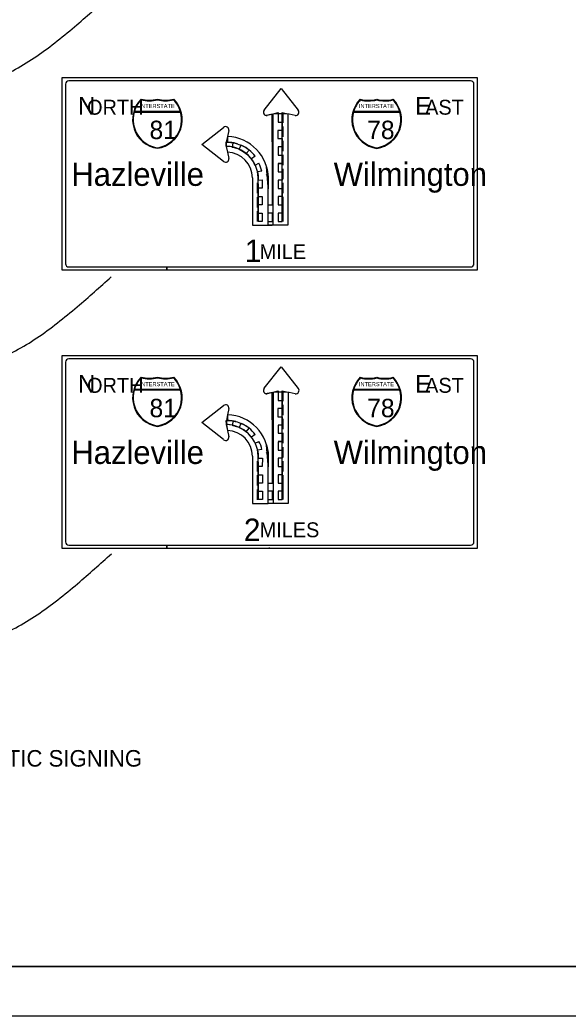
# Model space of a CAD drawing. Extents: x 640994 to 644422, y 298458 to 299646.
# Drawn here: x 642036.9 to 642202.5, y 298457.6 to 298758.5 of the extents above; entities that cross this region are included whole.
import ezdxf

# ---------------------------------------------------------------- set-up
doc = ezdxf.new("R2010")
doc.units = 0
for name, color, linetype in [('1', 7, 'Continuous'), ('2', 7, 'Continuous'), ('XCS-GRID-MIN', 7, 'Continuous')]:
    doc.layers.add(name, color=color, linetype=linetype)

msp = doc.modelspace()

# ---------------------------------------------------------------- linework, layer by layer
at = {"layer": '1'}
for p, q in [((642661.31, 298472.63), (641875.31, 298472.63)), ((641875.31, 298472.63), (642461.31, 298472.63))]:
    msp.add_line(p, q, dxfattribs=at)
at = {"layer": '2'}
for p, q in [((642049.69, 298682.88), (642049.69, 298741.13)), ((642049.69, 298741.13), (642175.06, 298741.13)), ((642049.69, 298740.13), (642049.69, 298740.13)), ((642050.69, 298739.13), (642050.69, 298684.88)), ((642173.06, 298740.13), (642051.69, 298740.13)), ((642174.06, 298684.88), (642174.06, 298739.13)), ((642175.06, 298741.13), (642175.06, 298682.88)), ((642175.06, 298740.13), (642175.06, 298740.13)), ((642110.71, 298731.28), (642115.83, 298737.78)), ((642115.83, 298737.78), (642120.98, 298731.22)), ((642073.56, 298734.38), (642073.56, 298734.38)), ((642078.44, 298734.38), (642078.44, 298734.38)), ((642083.31, 298734.38), (642083.31, 298734.38)), ((642139.81, 298734.38), (642139.81, 298734.38)), ((642144.69, 298734.38), (642144.69, 298734.38)), ((642149.56, 298734.38), (642149.56, 298734.38)), ((642061.94, 298732.13), (642061.94, 298732.13)), ((642061.94, 298732.13), (642061.94, 298732.13)), ((642061.94, 298732.13), (642061.94, 298732.13)), ((642061.94, 298732.13), (642061.94, 298732.13)), ((642061.94, 298732.13), (642061.94, 298732.13)), ((642071.44, 298730.63), (642085.44, 298730.63)), ((642085.44, 298730.88), (642071.56, 298730.88)), ((642110.69, 298731.22), (642110.71, 298731.28)), ((642113.13, 298730), (642111.25, 298729.63)), ((642113.46, 298730.03), (642111.58, 298729.65)), ((642113.46, 298730.03), (642111.61, 298729.63)), ((642113.13, 298730.03), (642114.88, 298730.52)), ((642114.94, 298730.15), (642113.46, 298730.03)), ((642113.46, 298696.53), (642113.46, 298730.03)), ((642114.88, 298730.52), (642114.88, 298727.62)), ((642116.1, 298730.15), (642114.94, 298730.15)), ((642118.21, 298730.03), (642116.1, 298730.15)), ((642116.13, 298697.65), (642116.13, 298730.53)), ((642116.13, 298730.53), (642117.88, 298730.1)), ((642116.13, 298727.38), (642116.13, 298730.5)), ((642116.46, 298727.4), (642116.46, 298730.53)), ((642117.88, 298730.1), (642117.88, 298696.5)), ((642120.06, 298729.63), (642118.21, 298730.03)), ((642151.69, 298730.88), (642137.69, 298730.88)), ((642137.69, 298730.63), (642151.69, 298730.63)), ((642162.81, 298732.13), (642162.81, 298732.13)), ((642162.81, 298732.13), (642162.81, 298732.13)), ((642078.44, 298727.13), (642078.44, 298727.13)), ((642114.88, 298727.62), (642116.11, 298727.62)), ((642116.11, 298727.62), (642116.11, 298725.13)), ((642144.69, 298727.13), (642144.69, 298727.13)), ((642091.88, 298720.9), (642098.38, 298726.03)), ((642100, 298725.15), (642099.63, 298723.28)), ((642116.11, 298725.13), (642114.81, 298725.13)), ((642114.81, 298725.13), (642114.81, 298722.67)), ((642116.13, 298723.13), (642116.13, 298726.25)), ((642116.46, 298723.15), (642116.46, 298726.28)), ((642098.38, 298715.78), (642091.88, 298720.9)), ((642099.63, 298723.27), (642099.25, 298721.55)), ((642099.25, 298721.53), (642099.25, 298720.28)), ((642114.81, 298722.67), (642116.12, 298722.67)), ((642116.12, 298722.67), (642116.12, 298720.14)), ((642116.13, 298718.88), (642116.13, 298722)), ((642116.46, 298718.9), (642116.46, 298722.03)), ((642099.22, 298720.32), (642099.63, 298718.52)), ((642099.25, 298720.28), (642099.63, 298718.53)), ((642099.63, 298718.53), (642100, 298716.65)), ((642116.12, 298720.14), (642114.88, 298720.14)), ((642114.88, 298720.14), (642114.88, 298717.69)), ((642114.88, 298717.69), (642116.14, 298717.69)), ((642116.13, 298714.63), (642116.13, 298717.75)), ((642116.14, 298717.69), (642116.14, 298715.15)), ((642116.46, 298714.65), (642116.46, 298717.78)), ((642107.96, 298717.31), (642106.85, 298716.51)), ((642107.98, 298714.65), (642109.08, 298715.22)), ((642116.14, 298715.15), (642114.88, 298715.15)), ((642114.88, 298715.15), (642114.88, 298715.15)), ((642114.88, 298715.15), (642116.11, 298715.15)), ((642116.11, 298715.14), (642114.88, 298715.14)), ((642114.88, 298715.14), (642114.88, 298712.63)), ((642116.11, 298715.15), (642116.11, 298715.14)), ((642109.98, 298712.79), (642108.66, 298712.63)), ((642111.42, 298714.08), (642111.39, 298714.15)), ((642111.39, 298714.15), (642111.6, 298713.35)), ((642111.87, 298711.17), (642111.4, 298711.94)), ((642111.4, 298711.94), (642111.88, 298711.08)), ((642111.6, 298713.35), (642111.72, 298712.74)), ((642111.72, 298712.74), (642111.83, 298711.84)), ((642111.83, 298711.84), (642111.87, 298711.17)), ((642114.88, 298712.63), (642116.13, 298712.63)), ((642116.13, 298710.38), (642116.13, 298713.5)), ((642116.13, 298712.63), (642116.13, 298710.15)), ((642116.46, 298710.4), (642116.46, 298713.53)), ((642107.13, 298710.78), (642107.13, 298696.5)), ((642108.55, 298709.25), (642108.55, 298706.13)), ((642108.9, 298697.66), (642108.86, 298710.83)), ((642108.87, 298709.04), (642108.88, 298706.15)), ((642110.12, 298710.16), (642110.11, 298707.65)), ((642111.87, 298696.5), (642111.88, 298710.5)), ((642111.87, 298707.53), (642111.88, 298709.23)), ((642111.88, 298710.5), (642111.88, 298710.72)), ((642116.13, 298710.15), (642114.88, 298710.15)), ((642114.88, 298710.15), (642114.88, 298707.63)), ((642116.13, 298706.13), (642116.13, 298709.25)), ((642116.46, 298706.15), (642116.46, 298709.28)), ((642110.11, 298707.65), (642108.87, 298707.65)), ((642114.88, 298707.63), (642116.12, 298707.63)), ((642116.12, 298707.63), (642116.12, 298705.14)), ((642108.55, 298705), (642108.55, 298701.88)), ((642108.89, 298705.15), (642108.88, 298701.9)), ((642110.12, 298702.65), (642108.88, 298702.65)), ((642110.12, 298705.15), (642110.12, 298702.65)), ((642116.12, 298705.14), (642114.91, 298705.14)), ((642114.91, 298705.14), (642114.91, 298702.64)), ((642114.91, 298702.64), (642116.13, 298702.64)), ((642116.13, 298701.88), (642116.13, 298705)), ((642116.46, 298701.9), (642116.46, 298705.03)), ((642108.55, 298700.75), (642108.55, 298697.63)), ((642108.88, 298700.78), (642108.88, 298697.65)), ((642110.12, 298700.16), (642110.13, 298697.65)), ((642114.89, 298700.18), (642114.89, 298697.65)), ((642116.13, 298700.75), (642116.13, 298701.88)), ((642116.13, 298697.63), (642116.13, 298700.75)), ((642116.46, 298700.78), (642116.46, 298701.9)), ((642116.46, 298697.65), (642116.46, 298700.78)), ((642110.13, 298697.65), (642108.9, 298697.66)), ((642111.87, 298697.65), (642113.17, 298697.65)), ((642114.89, 298697.65), (642116.13, 298697.65)), ((642107.13, 298696.5), (642111.87, 298696.5)), ((642111.9, 298696.53), (642113.13, 298696.53)), ((642117.88, 298696.5), (642113.17, 298696.5)), ((642081.33, 298682.88), (642049.69, 298682.88)), ((642051.69, 298683.88), (642081.33, 298683.88)), ((642081.33, 298683.88), (642081.33, 298682.88)), ((642081.33, 298682.88), (642081.33, 298683.88)), ((642081.33, 298683.88), (642173.06, 298683.88)), ((642175.06, 298682.88), (642081.33, 298682.88)), ((642112.31, 298682.88), (642112.31, 298683.13)), ((642049.69, 298657.13), (642049.69, 298657.13)), ((642049.69, 298598.88), (642049.69, 298657.13)), ((642049.69, 298657.13), (642175.06, 298657.13)), ((642050.69, 298655.13), (642050.69, 298600.88)), ((642173.06, 298656.13), (642051.69, 298656.13)), ((642174.06, 298600.88), (642174.06, 298655.13)), ((642175.06, 298657.13), (642175.06, 298657.13)), ((642175.06, 298657.13), (642175.06, 298598.88)), ((642110.73, 298647.25), (642115.86, 298653.75)), ((642115.86, 298653.75), (642121, 298647.19)), ((642073.56, 298650.38), (642073.56, 298650.38)), ((642078.44, 298650.38), (642078.44, 298650.38)), ((642083.31, 298650.38), (642083.31, 298650.38)), ((642139.81, 298650.38), (642139.81, 298650.38)), ((642144.69, 298650.38), (642144.69, 298650.38)), ((642149.56, 298650.38), (642149.56, 298650.38)), ((642061.94, 298648.13), (642061.94, 298648.13)), ((642061.94, 298648.13), (642061.94, 298648.13)), ((642061.94, 298648.13), (642061.94, 298648.13)), ((642061.94, 298648.13), (642061.94, 298648.13)), ((642061.94, 298648.13), (642061.94, 298648.13)), ((642061.94, 298648.13), (642061.94, 298648.13)), ((642071.44, 298646.75), (642085.44, 298646.75)), ((642085.44, 298646.88), (642071.56, 298646.88)), ((642110.71, 298647.19), (642110.73, 298647.25)), ((642113.15, 298645.97), (642111.28, 298645.6)), ((642113.48, 298646), (642111.61, 298645.62)), ((642113.48, 298646), (642111.63, 298645.6)), ((642113.15, 298646), (642114.9, 298646.49)), ((642114.96, 298646.12), (642113.48, 298646)), ((642113.48, 298612.5), (642113.48, 298646)), ((642114.9, 298646.49), (642114.9, 298643.59)), ((642116.12, 298646.12), (642114.96, 298646.12)), ((642118.23, 298646), (642116.12, 298646.12)), ((642116.15, 298613.62), (642116.15, 298646.5)), ((642116.15, 298646.5), (642117.9, 298646.08)), ((642116.15, 298643.35), (642116.15, 298646.47)), ((642116.48, 298643.37), (642116.48, 298646.5)), ((642117.9, 298646.08), (642117.9, 298612.47)), ((642120.08, 298645.6), (642118.23, 298646)), ((642151.69, 298646.88), (642137.69, 298646.88)), ((642137.69, 298646.75), (642151.69, 298646.75)), ((642162.81, 298648.13), (642162.81, 298648.13)), ((642078.44, 298643.13), (642078.44, 298643.13)), ((642114.9, 298643.59), (642116.13, 298643.59)), ((642116.13, 298643.59), (642116.13, 298641.1)), ((642144.69, 298643.13), (642144.69, 298643.13)), ((642091.9, 298636.87), (642098.4, 298642)), ((642100.02, 298641.12), (642099.65, 298639.25)), ((642116.13, 298641.1), (642114.83, 298641.1)), ((642114.83, 298641.1), (642114.83, 298638.64)), ((642116.15, 298639.1), (642116.15, 298642.22)), ((642116.48, 298639.12), (642116.48, 298642.25)), ((642098.4, 298631.75), (642091.9, 298636.87)), ((642099.65, 298639.24), (642099.27, 298637.52)), ((642099.27, 298637.5), (642099.27, 298636.25)), ((642114.83, 298638.64), (642116.14, 298638.64)), ((642116.14, 298638.64), (642116.14, 298636.11)), ((642116.15, 298634.85), (642116.15, 298637.97)), ((642116.48, 298634.87), (642116.48, 298638)), ((642099.24, 298636.29), (642099.65, 298634.49)), ((642099.27, 298636.25), (642099.65, 298634.5)), ((642099.65, 298634.5), (642100.02, 298632.62)), ((642116.14, 298636.11), (642114.9, 298636.11)), ((642114.9, 298636.11), (642114.9, 298633.66)), ((642114.9, 298633.66), (642116.16, 298633.66)), ((642116.15, 298630.6), (642116.15, 298633.72)), ((642116.16, 298633.66), (642116.16, 298631.12)), ((642116.48, 298630.62), (642116.48, 298633.75)), ((642107.98, 298633.28), (642106.88, 298632.48)), ((642108, 298630.62), (642109.1, 298631.2)), ((642116.16, 298631.12), (642114.9, 298631.12)), ((642114.9, 298631.12), (642114.9, 298631.12)), ((642114.9, 298631.12), (642116.13, 298631.12)), ((642116.13, 298631.11), (642114.9, 298631.11)), ((642114.9, 298631.11), (642114.9, 298628.6)), ((642116.13, 298631.12), (642116.13, 298631.11)), ((642110, 298628.77), (642108.69, 298628.6)), ((642111.44, 298630.05), (642111.41, 298630.12)), ((642111.41, 298630.12), (642111.62, 298629.32)), ((642111.89, 298627.14), (642111.42, 298627.91)), ((642111.42, 298627.91), (642111.9, 298627.05)), ((642111.62, 298629.32), (642111.74, 298628.71)), ((642111.74, 298628.71), (642111.86, 298627.81)), ((642111.86, 298627.81), (642111.89, 298627.14)), ((642114.9, 298628.6), (642116.15, 298628.6)), ((642116.15, 298626.35), (642116.15, 298629.47)), ((642116.15, 298628.6), (642116.15, 298626.12)), ((642116.48, 298626.37), (642116.48, 298629.5)), ((642107.15, 298626.75), (642107.15, 298612.47)), ((642108.57, 298625.22), (642108.57, 298622.1)), ((642108.92, 298613.63), (642108.88, 298626.8)), ((642108.9, 298625.01), (642108.9, 298622.12)), ((642110.14, 298626.13), (642110.13, 298623.62)), ((642111.89, 298612.47), (642111.9, 298626.47)), ((642111.89, 298623.5), (642111.9, 298625.2)), ((642111.9, 298626.47), (642111.9, 298626.69)), ((642116.15, 298626.12), (642114.9, 298626.12)), ((642114.9, 298626.12), (642114.9, 298623.6)), ((642116.15, 298622.1), (642116.15, 298625.22)), ((642116.48, 298622.12), (642116.48, 298625.25)), ((642110.13, 298623.62), (642108.89, 298623.62)), ((642114.9, 298623.6), (642116.14, 298623.6)), ((642116.14, 298623.6), (642116.14, 298621.11)), ((642108.57, 298620.97), (642108.57, 298617.85)), ((642108.91, 298621.12), (642108.9, 298617.87)), ((642110.14, 298618.62), (642108.9, 298618.62)), ((642110.14, 298621.12), (642110.14, 298618.62)), ((642116.14, 298621.11), (642114.93, 298621.11)), ((642114.93, 298621.11), (642114.93, 298618.61)), ((642114.93, 298618.61), (642116.15, 298618.61)), ((642116.15, 298617.85), (642116.15, 298620.97)), ((642116.48, 298617.87), (642116.48, 298621)), ((642108.57, 298616.72), (642108.57, 298613.6)), ((642108.9, 298616.75), (642108.9, 298613.62)), ((642110.14, 298616.13), (642110.15, 298613.62)), ((642114.91, 298616.15), (642114.91, 298613.62)), ((642116.15, 298616.72), (642116.15, 298617.85)), ((642116.15, 298613.6), (642116.15, 298616.72)), ((642116.48, 298616.75), (642116.48, 298617.87)), ((642116.48, 298613.62), (642116.48, 298616.75)), ((642107.15, 298612.47), (642111.89, 298612.47)), ((642110.15, 298613.62), (642108.92, 298613.63)), ((642111.89, 298613.62), (642113.19, 298613.62)), ((642111.92, 298612.5), (642113.15, 298612.5)), ((642117.9, 298612.47), (642113.19, 298612.47)), ((642114.91, 298613.62), (642116.15, 298613.62)), ((642081.33, 298598.88), (642049.69, 298598.88)), ((642051.69, 298599.88), (642081.33, 298599.88)), ((642081.33, 298599.88), (642081.33, 298598.88)), ((642081.33, 298598.88), (642081.33, 298599.88)), ((642081.33, 298599.88), (642173.06, 298599.88)), ((642175.06, 298598.88), (642081.33, 298598.88)), ((642112.31, 298598.88), (642112.31, 298599.13))]:
    msp.add_line(p, q, dxfattribs=at)
for points in [[(642113.17, 298696.5), (642111.87, 298696.5), (642111.87, 298697.65), (642113.17, 298697.65), (642113.17, 298700.15), (642111.87, 298700.15), (642111.88, 298702.65), (642113.17, 298702.65), (642113.17, 298707.6), (642113.19, 298713.26), (642113.13, 298730.03)], [(642103.35, 298719.33), (642103.42, 298719.3), (642103.11, 298719.44), (642102.45, 298719.74), (642101.86, 298719.92), (642101.52, 298720.02), (642100.41, 298720.23), (642099.81, 298720.29), (642099.25, 298720.33), (642099.24, 298721.56), (642099.83, 298721.56), (642100.66, 298721.5), (642101.92, 298721.27), (642102.55, 298721.09), (642103.04, 298720.9), (642103.9, 298720.56), (642103.81, 298720.6)], [(642099.63, 298723.27), (642099.61, 298721.54), (642099.25, 298721.55)], [(642102.63, 298721.05), (642102.24, 298721.18), (642102.09, 298721.21), (642101.64, 298721.33), (642101.38, 298721.39), (642101.26, 298721.41), (642101.01, 298720.11), (642101.21, 298720.08), (642101.45, 298720.05), (642101.76, 298719.92), (642101.82, 298719.9), (642101.82, 298719.9), (642101.82, 298719.91), (642101.95, 298719.87), (642101.99, 298719.86), (642101.97, 298719.9), (642101.99, 298719.85), (642102.25, 298719.77)], [(642106.13, 298719.19), (642105.11, 298719.92), (642103.96, 298720.56), (642103.65, 298720.68), (642103.17, 298719.43), (642104.33, 298718.81), (642105.43, 298717.98), (642105.61, 298717.83), (642105.69, 298717.76), (642105.71, 298717.75)], [(642106.33, 298717.12), (642106.49, 298716.94), (642105.94, 298717.53), (642105.15, 298718.24), (642105.25, 298718.13), (642106.14, 298719.21), (642106.12, 298719.21), (642106.14, 298719.19), (642106.1, 298719.22)], [(642108.66, 298712.63), (642108.84, 298711.47), (642108.89, 298710.15), (642110.12, 298710.16)], [(642111.88, 298711.08), (642111.88, 298708.23), (642111.42, 298714.08)], [(642111.88, 298710.55), (642111.88, 298707.65), (642111.87, 298707.53)], [(642111.88, 298710.72), (642111.88, 298710.72), (642111.88, 298710.55)], [(642111.88, 298709.23), (642111.89, 298710.14), (642111.88, 298710.5)], [(642108.87, 298707.65), (642108.89, 298705.14), (642110.12, 298705.15)], [(642108.88, 298702.65), (642108.88, 298700.16), (642110.12, 298700.16)], [(642116.13, 298702.64), (642116.13, 298700.18), (642114.89, 298700.18)], [(642113.19, 298612.47), (642111.89, 298612.47), (642111.89, 298613.62), (642113.19, 298613.62), (642113.19, 298616.12), (642111.9, 298616.12), (642111.9, 298618.62), (642113.19, 298618.62), (642113.2, 298623.57), (642113.21, 298629.23), (642113.15, 298646)], [(642103.37, 298635.3), (642103.44, 298635.28), (642103.14, 298635.41), (642102.47, 298635.71), (642101.88, 298635.9), (642101.54, 298635.99), (642100.43, 298636.2), (642099.84, 298636.26), (642099.27, 298636.3), (642099.26, 298637.53), (642099.86, 298637.53), (642100.68, 298637.47), (642101.94, 298637.24), (642102.57, 298637.06), (642103.07, 298636.87), (642103.92, 298636.53), (642103.83, 298636.57)], [(642099.65, 298639.24), (642099.63, 298637.51), (642099.27, 298637.52)], [(642102.65, 298637.02), (642102.26, 298637.15), (642102.11, 298637.18), (642101.66, 298637.3), (642101.4, 298637.36), (642101.28, 298637.38), (642101.04, 298636.08), (642101.23, 298636.05), (642101.47, 298636.02), (642101.78, 298635.89), (642101.84, 298635.87), (642101.84, 298635.87), (642101.84, 298635.88), (642101.97, 298635.84), (642102.01, 298635.83), (642101.99, 298635.87), (642102.01, 298635.82), (642102.27, 298635.74)], [(642106.15, 298635.16), (642105.13, 298635.9), (642103.99, 298636.53), (642103.67, 298636.65), (642103.19, 298635.41), (642104.36, 298634.78), (642105.45, 298633.95), (642105.63, 298633.8), (642105.72, 298633.73), (642105.73, 298633.72)], [(642106.35, 298633.09), (642106.51, 298632.91), (642105.96, 298633.5), (642105.17, 298634.21), (642105.27, 298634.1), (642106.16, 298635.18), (642106.14, 298635.18), (642106.16, 298635.16), (642106.12, 298635.19)], [(642108.69, 298628.6), (642108.86, 298627.44), (642108.91, 298626.12), (642110.14, 298626.13)], [(642111.9, 298627.05), (642111.9, 298624.2), (642111.44, 298630.05)], [(642111.9, 298626.53), (642111.9, 298623.62), (642111.89, 298623.5)], [(642111.9, 298626.69), (642111.9, 298626.69), (642111.9, 298626.53)], [(642111.9, 298625.2), (642111.92, 298626.11), (642111.9, 298626.47)], [(642108.89, 298623.62), (642108.91, 298621.11), (642110.14, 298621.12)], [(642108.9, 298618.62), (642108.9, 298616.13), (642110.14, 298616.13)], [(642116.15, 298618.61), (642116.15, 298616.15), (642114.91, 298616.15)]]:
    msp.add_lwpolyline(points, dxfattribs=at)
for centre, radius, start, end in [((642051.69, 298739.13), 1, 90, 180), ((642173.06, 298739.13), 1, 0, 90), ((642079.68, 298728.38), 8.74, 135, 261.8699), ((642079.68, 298728.38), 8.56, 135.6924, 163.2072), ((642075.97, 298744.3), 10.04, 255.75, 284.25), ((642075.97, 298744.3), 10.23, 256.3405, 283.989), ((642080.91, 298744.3), 10.04, 255.75, 284.25), ((642077.2, 298728.38), 8.74, 278.1301, 45), ((642080.91, 298744.3), 10.23, 256.011, 283.6595), ((642077.2, 298728.38), 8.56, 16.7928, 44.3076), ((642145.92, 298728.36), 8.74, 135, 261.8699), ((642145.92, 298728.36), 8.56, 135.6924, 163.2072), ((642142.21, 298744.27), 10.04, 255.75, 284.25), ((642142.21, 298744.27), 10.23, 256.3405, 283.989), ((642147.16, 298744.27), 10.04, 255.75, 284.25), ((642143.45, 298728.36), 8.74, 278.1301, 45), ((642147.16, 298744.27), 10.23, 256.011, 283.6595), ((642143.45, 298728.36), 8.56, 16.7928, 44.3076), ((642079.68, 298728.38), 8.56, 164.4869, 261.8699), ((642077.2, 298728.38), 8.56, 278.1301, 15.5131), ((642111.43, 298730.59), 0.978, 139.8521, 280.5176), ((642120.23, 298730.59), 0.978, 259.4824, 40.1479), ((642145.92, 298728.36), 8.56, 164.4869, 261.8699), ((642143.45, 298728.36), 8.56, 278.1301, 15.5131), ((642099.06, 298725.3), 0.978, 349.4824, 130.1479), ((642099.38, 298710.78), 10.77, 72.4094, 90.6647), ((642099.24, 298710.64), 12.64, 359.3869, 88.2432), ((642099.14, 298710.59), 9.73, 1.3887, 89.5341), ((642099.38, 298710.78), 7.75, 0, 88.1454), ((642099.16, 298710.56), 9.72, 64.4539, 71.4499), ((642099.99, 298711.67), 9.71, 50.798, 66.8365), ((642100.28, 298711.71), 8.11, 41.8332, 48.0374), ((642100.14, 298711.57), 9.7, 36.2782, 52.0652), ((642099.06, 298716.5), 0.978, 229.8521, 10.5176), ((642095.04, 298708.06), 14.52, 26.999, 35.5695), ((642101.68, 298711.09), 8.48, 11.6278, 29.218), ((642051.69, 298684.88), 1, 180, 270), ((642173.06, 298684.88), 1, 270, 0), ((642051.69, 298655.13), 1, 90, 180), ((642173.06, 298655.13), 1, 0, 90), ((642079.68, 298644.4), 8.74, 135, 261.8699), ((642079.68, 298644.4), 8.56, 135.6924, 163.2072), ((642075.97, 298660.32), 10.04, 255.75, 284.25), ((642075.97, 298660.32), 10.23, 256.3405, 283.989), ((642080.91, 298660.32), 10.04, 255.75, 284.25), ((642077.2, 298644.4), 8.74, 278.1301, 45), ((642080.91, 298660.32), 10.23, 256.011, 283.6595), ((642077.2, 298644.4), 8.56, 16.7928, 44.3076), ((642145.92, 298644.38), 8.74, 135, 261.8699), ((642145.92, 298644.38), 8.56, 135.6924, 163.2072), ((642142.21, 298660.29), 10.04, 255.75, 284.25), ((642142.21, 298660.29), 10.23, 256.3405, 283.989), ((642147.16, 298660.29), 10.04, 255.75, 284.25), ((642143.45, 298644.38), 8.74, 278.1301, 45), ((642147.16, 298660.29), 10.23, 256.011, 283.6595), ((642143.45, 298644.38), 8.56, 16.7928, 44.3076), ((642079.68, 298644.4), 8.56, 164.4869, 261.8699), ((642077.2, 298644.4), 8.56, 278.1301, 15.5131), ((642111.46, 298646.56), 0.978, 139.8521, 280.5176), ((642120.26, 298646.56), 0.978, 259.4824, 40.1479), ((642145.92, 298644.38), 8.56, 164.4869, 261.8699), ((642143.45, 298644.38), 8.56, 278.1301, 15.5131), ((642099.08, 298641.27), 0.978, 349.4824, 130.1479), ((642099.4, 298626.75), 10.77, 72.4094, 90.6647), ((642099.26, 298626.61), 12.64, 359.3869, 88.2432), ((642100.01, 298627.64), 9.71, 50.798, 66.8365), ((642099.16, 298626.56), 9.73, 1.3887, 89.5341), ((642099.4, 298626.75), 7.75, 0, 88.1454), ((642099.18, 298626.53), 9.72, 64.4539, 71.4499), ((642100.3, 298627.68), 8.11, 41.8332, 48.0374), ((642100.16, 298627.54), 9.7, 36.2782, 52.0652), ((642099.08, 298632.47), 0.978, 229.8521, 10.5176), ((642095.06, 298624.03), 14.52, 26.999, 35.5695), ((642101.7, 298627.06), 8.48, 11.6278, 29.218), ((642051.69, 298600.88), 1, 180, 270), ((642173.06, 298600.88), 1, 270, 0)]:
    msp.add_arc(centre, radius, start, end, dxfattribs=at)
for points in [[(641995.94, 298762.88), (641998.23, 298754.26), (642010.49, 298739.55), (642027.72, 298740.15), (642041.21, 298747.03), (642053.43, 298756.45), (642063.69, 298765.5)], [(641996.75, 298678.29), (641999.04, 298669.68), (642011.3, 298654.97), (642028.53, 298655.56), (642042.03, 298662.45), (642054.24, 298671.87), (642064.5, 298680.92)], [(641996.82, 298594.65), (641999.12, 298586.04), (642011.37, 298571.33), (642028.6, 298571.92), (642042.1, 298578.81), (642054.31, 298588.23), (642064.57, 298597.28)]]:
    msp.add_spline(points, degree=3, dxfattribs=at)
at = {"layer": 'XCS-GRID-MIN'}
msp.add_lwpolyline([(641835.31, 299051.63), (642676.31, 299051.63), (642676.31, 298457.63), (641835.31, 298457.63)], close=True, dxfattribs=at)

# ---------------------------------------------------------------- texts
at = {"layer": '2'}
for s, height, p in [('N', 5.38, (642054.44, 298729.88)), ('ORTH', 4.5, (642057.19, 298729.88)), ('INTERSTATE', 1.236, (642073.06, 298731.88)), ('INTERSTATE', 1.236, (642139.31, 298731.88)), ('E', 5.38, (642156.31, 298729.88)), ('AST', 4.5, (642159.31, 298729.88)), ('81', 5.563, (642076.06, 298722.5)), ('78', 5.563, (642141.81, 298722.5)), ('Hazleville', 7, (642052.44, 298708.38)), ('Wilmington', 7, (642131.69, 298708.38)), ('1', 6.75, (642104.81, 298685.38)), ('MILE', 4.5, (642109.31, 298686.25)), ('N', 5.38, (642054.44, 298645.88)), ('ORTH', 4.5, (642057.19, 298645.88)), ('INTERSTATE', 1.236, (642073.06, 298647.88)), ('INTERSTATE', 1.236, (642139.31, 298647.88)), ('E', 5.38, (642156.31, 298645.88)), ('AST', 4.5, (642159.31, 298645.88)), ('81', 5.563, (642076.06, 298638.5)), ('78', 5.563, (642141.81, 298638.5)), ('Hazleville', 7, (642052.44, 298624.38)), ('Wilmington', 7, (642131.69, 298624.38)), ('2', 6.75, (642104.56, 298601.13)), ('MILES', 4.5, (642109.31, 298602.25)), ('DIAGRAMMATIC SIGNING', 5, (641991.72, 298532.97))]:
    msp.add_text(s, height=height, dxfattribs=at).set_placement(p)

doc.saveas('drawing.dxf')
